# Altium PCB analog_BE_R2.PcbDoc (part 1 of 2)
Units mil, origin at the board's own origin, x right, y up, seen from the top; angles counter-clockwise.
Board outline 3800 x 1200 mil, 2 copper layers (Top Layer, Bottom Layer), stack 62 mil thick; 98 components, 58 nets, 283 pads, 64 vias.
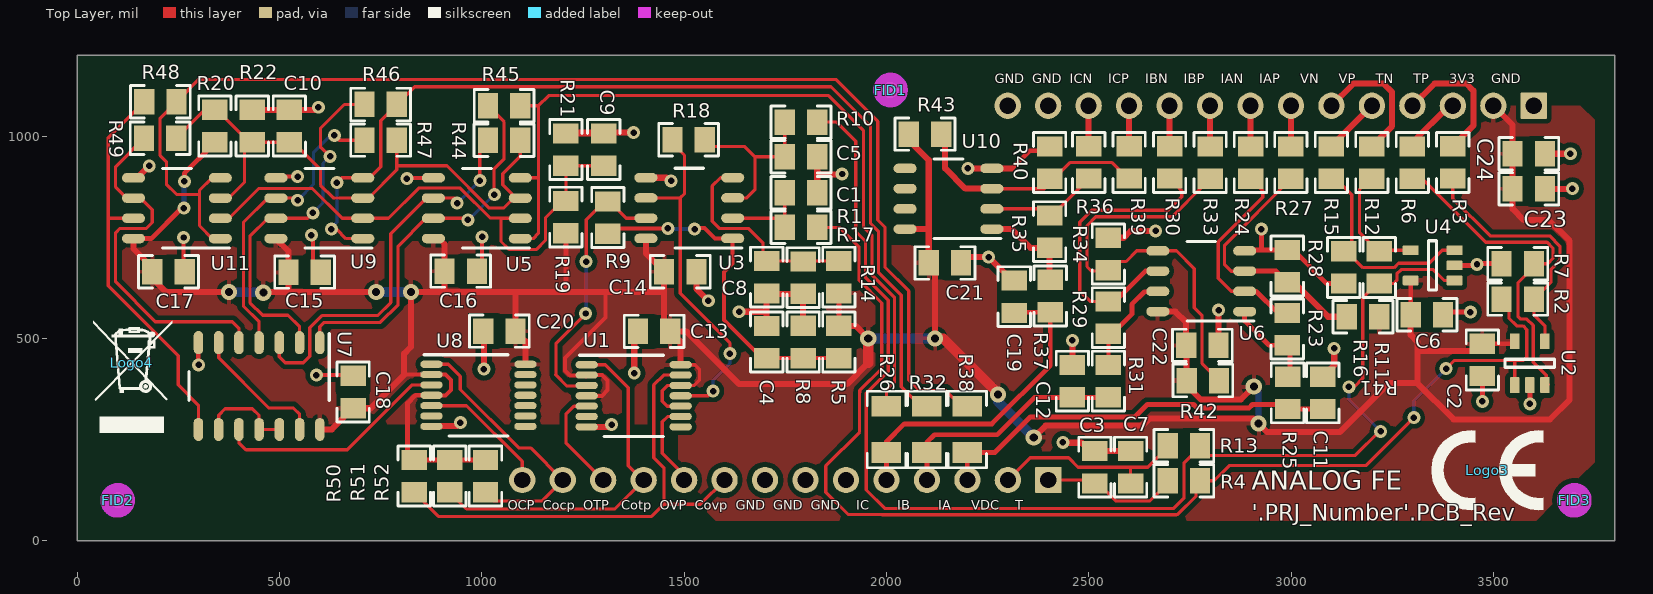
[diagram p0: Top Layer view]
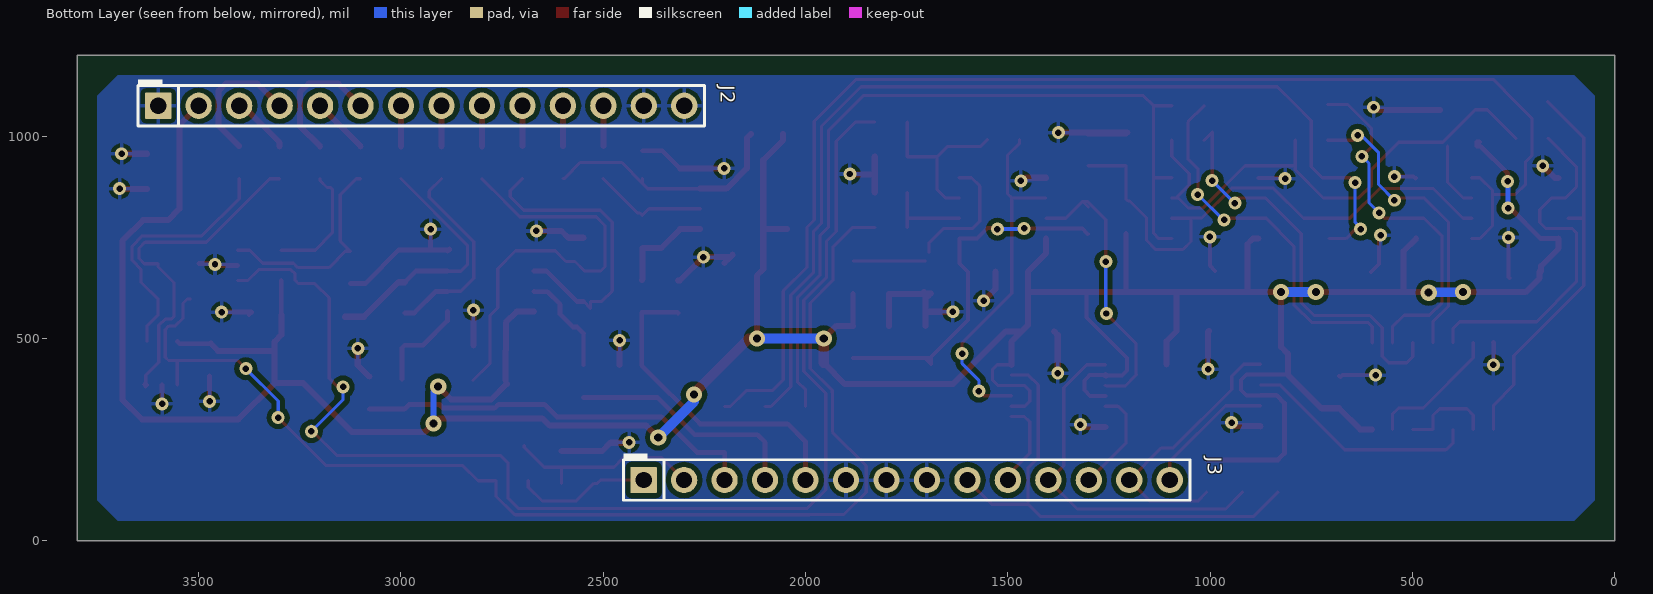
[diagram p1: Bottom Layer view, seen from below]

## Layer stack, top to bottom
Top Solder: solder mask 0.4, Solder Resist, Dk 3.5
Top Layer: signal copper 1.4
Dielectric1: core 59.2, FR-4, Dk 4.8
Bottom Layer: signal copper 1.4
Bottom Solder: solder mask 0.4, Solder Resist, Dk 3.5

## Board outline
0,0 0,1200 3800,1200 3800,0

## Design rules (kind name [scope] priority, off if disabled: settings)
AcuteAngle [All] p1: minimum=4.50000000000000E+0001 checktracksonly=FALSE
AssemblyTestPointUsage [All] p1: valid=2
BoardOutlineClearance BoardOutlineClearance_MountingHoles [OnCopper and InComponentClass('Mounting Holes')] p1: gap=39.37 ignorepadtopadclearanceinfootprint=FALSE
BoardOutlineClearance BoardOutlineClearance_Poly [OnCopper and IsPoly] p2: gap=25 ignorepadtopadclearanceinfootprint=FALSE
BoardOutlineClearance [OnCopper and Not InComponentClass('Logo') and not InComponentClass('FiducialMark') and not InRegion(1000,500,4000,800) and not InPoly] p3: gap=50 ignorepadtopadclearanceinfootprint=FALSE
Clearance Clearance_Keepouts [((IsTrack Or IsArc) And Not InPoly) And IsFree and IsKeepOut vs ((IsTrack Or IsArc) And Not InPoly) And IsFree and IsKeepOut] p1: gap=0 ignorepadtopadclearanceinfootprint=FALSE
Clearance Clearance_Poly [InPolygon] p2: gap=12 ignorepadtopadclearanceinfootprint=TRUE
Clearance Clearance_FiducialMark [IsKeepOut and InComponentClass('FiducialMark') vs IsPad and InComponentClass('FiducialMark')] p3: gap=0 ignorepadtopadclearanceinfootprint=FALSE
Clearance [All] p4: gap=7.87 ignorepadtopadclearanceinfootprint=TRUE
ComponentClearance ComponentClearance_MountingHoles_FiducialMarks [InComponentClass('Mounting Holes') vs InComponentClass('FiducialMark')] p1: gap=50 collisioncheckmode=3 verticalgap=10 showdistances=FALSE
ComponentClearance ComponentClearance_Shunt [InComponentClass('Header') vs InComponentClass('Shunt')] p2: gap=0 collisioncheckmode=3 verticalgap=0 showdistances=FALSE
ComponentClearance ComponentClearance_Logo [InComponentClass('Logo')] p3: gap=50 collisioncheckmode=3 verticalgap=10 showdistances=FALSE
ComponentClearance ComponentClearance_ScrewToNut [(HasFootprint('NY PMS 440 0025 PH')) vs (HasFootprint('Keystone_1902C'))] p4: gap=5 collisioncheckmode=3 verticalgap=10 showdistances=FALSE
ComponentClearance ComponentClearance_MountingHoles [InComponentClass('Mounting Holes')] p5: gap=250 collisioncheckmode=3 verticalgap=100000 showdistances=FALSE
ComponentClearance ComponentClearance_SmallPassives [HasFootprint('0201*') or HasFootprint('0402*') or HasFootprint('0508') or HasFootprint('0603*') or HasFootprint('0612') or HasFootprint('0805*') or HasFootprint('0815*') or HasFootprint('0830*') or HasFootprint('1206*') or HasFootprint('1210*') or HasFootprint('1808*') or HasFootprint('1812*') or HasFootprint('1825*') or HasFootprint('2010*') or HasFootprint('2220*') or HasFootprint('2225*') or HasFootprint('2512*') or HasFootprint('2728*') or HasFootprint('3518*') vs HasFootprint('0201*') or HasFootprint('0402*') or HasFootprint('0508') or HasFootprint('0603*') or HasFootprint('0612') or HasFootprint('0805*') or HasFootprint('0815*') or HasFootprint('0830*') or HasFootprint('1206*') or HasFootprint('1210*') or HasFootprint('1808*') or HasFootprint('1812*') or HasFootprint('1825*') or HasFootprint('2010*') or HasFootprint('2220*') or HasFootprint('2225*') or HasFootprint('2512*') or HasFootprint('2728*') or HasFootprint('3518*')] p6: gap=14.96 collisioncheckmode=3 verticalgap=10 showdistances=FALSE
ComponentClearance ComponentClearance_THtoSMT [IsThruComponent vs IsSMTComponent] p7: gap=40 collisioncheckmode=3 verticalgap=30 showdistances=FALSE
ComponentClearance ComponentClearance_THtoTH [IsThruComponent vs IsThruComponent] p8: gap=30 collisioncheckmode=3 verticalgap=30 showdistances=FALSE
ComponentClearance [All] p9: gap=30 collisioncheckmode=3 verticalgap=10 showdistances=FALSE
DiffPairsRouting [All] p1: maxlimit=100 minlimit=10 mostfreqgap=10 toplayer_minwidth=15 toplayer_maxwidth=15 toplayer_prefwidth=15 bottomlayer_minwidth=15 bottomlayer_maxwidth=15 bottomlayer_prefwidth=15 maxuncoupledlength=1000
FabricationTestPointUsage TestPointUsage [All] p1: valid=2 allowmultiple=FALSE
FabricationTestpoint Testpoint [All] p1: side=3 testpointundercomponent=TRUE minsize=40 maxsize=100 preferedsize=60 minholesize=0 maxholesize=40 preferedholesize=32 testpointgrid=1 allowsidetop=TRUE allowsidebottom=TRUE usegrid=TRUE gridtolerance=0.01
FanoutControl Fanout_LCC [IsLCC] p1: bgadir=Out bgaviamode=Centered fanoutstyle=Auto fanoutdirection=Alternating viagrid=1 // Fanout_LCC (Default Rule)
FanoutControl Fanout_BGA [IsBGA] p2: bgadir=Out bgaviamode=Centered fanoutstyle=Auto fanoutdirection=Alternating viagrid=1 // Fanout_BGA (Default Rule)
FanoutControl Fanout_Default [All] p4: bgadir=Out bgaviamode=Centered fanoutstyle=Auto fanoutdirection=Alternating viagrid=1 // Fanout_Default (Default Rule)
FanoutControl Fanout_Small [(CompPinCount < 5)] p5: bgadir=Out bgaviamode=Centered fanoutstyle=Auto fanoutdirection=OutThenIn viagrid=1 // Fanout_Small (Default Rule)
HoleSize [All] p1: absolutevalues=TRUE maxlimit=251 minlimit=7.87 maxpercent=80.000 minpercent=20.000
MinimumAnnularRing MinimumAnnularRing_ThermalPadVias [IsVia and InAnyComponent] p1: minimumring=5.91
MinimumAnnularRing [All] p2: minimumring=7.87
MinimumSolderMaskSliver MinimumSolderMaskSliver_Logo [InComponentClass('Logo') vs InComponentClass('Logo')] p1: minsoldermaskwidth=0.7
MinimumSolderMaskSliver [All] p2: minsoldermaskwidth=3.94
PlaneClearance [All] p1: clearance=12
PlaneConnect [All] p1: planeconnectstyle=Relief reliefexpansion=10 reliefentries=4 reliefconductorwidth=10 reliefairgap=10
PolygonConnect [All] p1: connectstyle=Relief reliefconductorwidth=10 reliefentries=4 polygonreliefangle="90 Angle" airgapwidth=10
RoutingVias ThermalPadVias [IsVia and InAnyComponent] p1: holewidth=7.87 width=19.68 viastyle="Through Hole" minholewidth=7.87 minwidth=19.68 maxholewidth=12.99 maxwidth=23.62
RoutingVias [All] p2: holewidth=16 width=34 viastyle="Through Hole" minholewidth=7.87 minwidth=26 maxholewidth=40 maxwidth=65
SilkToBoardRegionClearance [Not ((IsComment or IsDesignator) And (Hide <> 'False')) and not InRegion(1000,500,4000,800)] p1:
SilkToSilkClearance SilkToSilkClearance_Pb-FreeLogo [(HasFootprint('Pb-Free_Overlay_Medium') OR HasFootprint('Pb-Free_Overlay_Small')) vs (HasFootprint('Pb-Free_Overlay_Medium') OR HasFootprint('Pb-Free_Overlay_Small'))] p1: silktosilkclearance=0
SilkToSilkClearance [All] p2: silktosilkclearance=3.94
SilkToSolderMaskClearance SilkToComponentPadClearance [(IsPad or IsFill or IsRegion) and InAnycomponent] p1: minsilkscreentomaskgap=5 clearancetoexposedcopper=TRUE
SilkToSolderMaskClearance "Silk to Solder Mask Opening" [All] p2: minsilkscreentomaskgap=3.94 clearancetoexposedcopper=FALSE
SolderMaskExpansion [All] p1: expansion=1.97
UnRoutedNet [All] p1: checkbadconnections=TRUE
Width [All] p1: maxlimit=100 minlimit=6 preferedwidth=10 checkconnectedcopper=TRUE
13 further rules are at their usual default settings.

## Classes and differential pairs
component class Header: J2 J3 p1
component class FiducialMark: FID1 FID2 FID3
component class AssemblyNote: ZZ1 ZZ2 ZZ3 ZZ4
differential pair Vdc: +Vdc_P -Vdc_N
differential pair Temp: +Temp_P -Temp_N
differential pair Ic: +Ic_P -Ic_N
differential pair Ib: +Ib_P -Ib_N
differential pair Ia: +Ia_P -Ia_N

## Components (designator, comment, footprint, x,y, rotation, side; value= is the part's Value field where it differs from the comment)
C1 "08051C103JAT2A" 0805_HV 1788.88,860.33 r0 top value=0.01uF
C2 "GRM219R71C104KA01D" 0805_HV 3472.61,446.92 r270 top value=0.1uF
C3 "08051C103JAT2A" 0805_HV 2515,181.72 r90 top value=0.01uF
C4 "08051A330JAT2A" 0805_HV 1703.92,490.96 r90 top value=33pF
C5 "08051C103JAT2A" 0805_HV 1788.88,949.05 r0 top value=0.01uF
C6 "GRM219R71C104KA01D" 0805_HV 3335.53,558.54 r0 top value=0.1uF
C7 "08051C103JAT2A" 0805_HV 2603.26,181.72 r90 top value=0.01uF
C8 "08051A330JAT2A" 0805_HV 1703.92,651.26 r270 top value=33pF
C9 "08051A330JAT2A" 0805_HV 1301.58,966.62 r90 top value=33pF
C10 "08051A330JAT2A" 0805_HV 524.61,1025 r90 top value=33pF
C11 "08051C103JAT2A" 0805_HV 3077.97,365.45 r90 top value=0.01uF
C12 "08051C103JAT2A" 0805_HV 2459.66,394.41 r90 top value=0.01uF
C13 "GRM219R71C104KA01D" 0805_HV 1425.84,517.29 r0 top value=0.1uF
C14 "GRM219R71C104KA01D" 0805_HV 1490.42,665 r180 top value=0.1uF
C15 "GRM219R71C104KA01D" 0805_HV 562.23,664.06 r180 top value=0.1uF
C16 "GRM219R71C104KA01D" 0805_HV 947.84,666.5 r180 top value=0.1uF
C17 "GRM219R71C104KA01D" 0805_HV 225.81,665 r180 top value=0.1uF
C18 "GRM219R71C104KA01D" 0805_HV 681.74,367.45 r270 top value=0.1uF
C19 "08051C103JAT2A" 0805_HV 2315.58,603.1 r90 top value=0.01uF
C20 "GRM219R71C104KA01D" 0805_HV 1043.31,518.09 r0 top value=0.1uF
C21 "GRM219R71C104KA01D" 0805_HV 2144.42,686.41 r180 top value=0.1uF
C22 "GRM219R71C104KA01D" 0805_HV 2780.65,482.64 r180 top value=0.1uF
C23 "GRM219R71C104KA01D" 0805_HV 3587.32,869.41 r180 top value=0.1uF
C24 "0805YD106MAT2A" 0805_HV 3587.32,956.29 r0 top value=10uF
FID1 "Fiducial" Fiducial10-20 2009.84,1113.85 r0 top
FID2 "Fiducial" Fiducial10-20 100,100 r0 top
FID3 "Fiducial" Fiducial10-20 3700,100 r0 top
J2 "TSW-114-07-G-S" TSW-114-07-G-S 2949.66,1075 r180 bottom
J3 "TSW-114-07-G-S" TSW-114-07-G-S 1750,150 r180 bottom
Logo3 "CE Mark" CE_Mark_5mm 3484.68,174.27 r0 top
Logo4 "WEEE logo" WEEE_Minimum 135,439.71 r0 top
R1 "CRCW0805100RDHEAP" 0805_HV 1788.88,774.42 r180 top value=100
R2 "RT0805BRD0747KL" 0805_HV 3560,597.1 r180 top value=47.0k
R3 "RG2012P-103-B-T5" 0805_HV 3399.66,935 r270 top value=10.0k
R4 "CRCW0805100RDHEAP" 0805_HV 2735,148.21 r180 top value=100
R5 "RR1220P-3321-D-M" 0805_HV 1882.6,491.05 r90 top value=3.32k
R6 "RG2012P-103-B-T5" 0805_HV 3299.66,934.53 r270 top value=10.0k
R7 "RT0805BRD0747KL" 0805_HV 3560,684.76 r0 top value=47.0k
R8 "RG2012P-3322-B-T5" 0805_HV 1794.1,491.05 r270 top value=33.2k
R9 "RR1220P-104-D" 0805_HV 1311.53,798.57 r270 top value=100k
R10 "CRCW0805100RDHEAP" 0805_HV 1788.88,1034.49 r180 top value=100
R11 "RT0805BRD0715KL" 0805_HV 3217.62,675.43 r270 top value=15.0k
R12 "RG2012P-103-B-T5" 0805_HV 3199.66,934.53 r270 top value=10.0k
R13 "CRCW0805100RDHEAP" 0805_HV 2735,235 r180 top value=100
R14 "RR1220P-7871-D-M" 0805_HV 1882.6,651.27 r270 top value=7.87k
R15 "RG2012P-103-B-T5" 0805_HV 3099.66,934.53 r270 top value=10.0k
R16 "RT0805BRD0715KL" 0805_HV 3129.66,675.43 r90 top value=15.0k
R17 "RG2012P-3322-B-T5" 0805_HV 1794.1,650.11 r90 top value=33.2k
R18 "RR1220P-104-D" 0805_HV 1511.15,990.85 r0 top value=100k
R19 "RR1220P-3321-D-M" 0805_HV 1207.81,799.63 r270 top value=3.32k
R20 "RG2012P-3322-B-T5" 0805_HV 340.37,1025 r270 top value=33.2k
R21 "RG2012P-3322-B-T5" 0805_HV 1207.81,966.62 r270 top value=33.2k
R22 "RR1220P-3321-D-M" 0805_HV 432.65,1025 r90 top value=3.32k
R23 "RT0805BRD077K5L" 0805_HV 2990.51,523.1 r270 top value=7.50k
R24 "MCU0805MD1002BP100" 0805_HV 2899.66,934.53 r270 top value=10.0k
R25 "CRCW0805100RDHEAP" 0805_HV 2991.08,365.45 r270 top value=100
R26 "CRCW12061K00FKEA" 1206 2000,275 r90 top value=1.00k
R27 "MCU0805MD1002BP100" 0805_HV 2999.66,934.53 r270 top value=10.0k
R28 "RT0805BRD0715KL" 0805_HV 2990.51,678.81 r270 top value=15.0k
R29 "RT0805BRD077K5L" 0805_HV 2548.35,551.37 r270 top value=7.50k
R30 "MCU0805MD1002BP100" 0805_HV 2699.66,935 r270 top value=10.0k
R31 "CRCW0805100RDHEAP" 0805_HV 2548.35,394.41 r270 top value=100
R32 "CRCW12061K00FKEA" 1206 2100,275 r90 top value=1.00k
R33 "MCU0805MD1002BP100" 0805_HV 2799.76,934.53 r270 top value=10.0k
R34 "RT0805BRD0715KL" 0805_HV 2548.35,708.7 r270 top value=15.0k
R35 "RT0805BRD077K5L" 0805_HV 2403.18,763.89 r270 top value=7.50k
R36 "MCU0805MD1002BP100" 0805_HV 2499.66,935 r270 top value=10.0k
R37 "CRCW0805100RDHEAP" 0805_HV 2404.66,604.81 r270 top value=100
R38 "CRCW12061K00FKEA" 1206 2199.66,275 r90 top value=1.00k
R39 "MCU0805MD1002BP100" 0805_HV 2599.66,935 r270 top value=10.0k
R40 "RT0805BRD0715KL" 0805_HV 2403.18,934.53 r270 top value=15.0k
R41 "RT0805BRD0715KL" 0805_HV 3177.62,553.6 r180 top value=15.0k
R42 "RT0805BRD0715KL" 0805_HV 2781.94,395.95 r0 top value=15.0k
R43 "RT0805BRD0715KL" 0805_HV 2095.22,1005 r0 top value=15.0k
R44 "RR1220P-104-D" 0805_HV 1055.03,989.91 r0 top value=100k
R45 "RR1220P-104-D" 0805_HV 1055.14,1075 r180 top value=100k
R46 "RR1220P-104-D" 0805_HV 750,1078.07 r180 top value=100k
R47 "RR1220P-104-D" 0805_HV 750,990 r0 top value=100k
R48 "RR1220P-104-D" 0805_HV 205.63,1085 r180 top value=100k
R49 "RR1220P-104-D" 0805_HV 205,994.43 r180 top value=100k
R50 "RT0805BRD0715KL" 0805_HV 832.83,159.81 r90 top value=15.0k
R51 "RT0805BRD0715KL" 0805_HV 920.58,159.81 r90 top value=15.0k
R52 "RT0805BRD0715KL" 0805_HV 1009.12,159.81 r90 top value=15.0k
U1 "SN74LVC74AQPWRQ1" PW0014A_N 1375.34,358.23 r0 top
U2 "TLV6001IDBVR" DBV0005A_N 3589.92,438.81 r90 top
U3 "TLV3502AID" D0008A_N 1512.77,822.11 r180 top
U4 "TLV6001IDBVR" DBV0005A_N 3349.66,680.49 r180 top
U5 "TLV3502AID" D0008A_N 987.74,821.8 r180 top
U6 "OPA2350UA/2K5" D0008A_N 2777.88,641.37 r180 top
U7 "CD74HC4075MT" D0014A_N 449.66,382.28 r270 top
U8 "SN74LVC74AQPWRQ1" PW0014A_N 991.67,359.41 r0 top
U9 "TLV3502AID" D0008A_N 598.5,821.8 r180 top
U10 "OPA2350UA/2K5" D0008A_N 2153.18,845.15 r180 top
U11 "TLV3502AID" D0008A_N 246.54,821.8 r180 top
ZZ1 "This Assembly Note is for PCB labels only" AssemblyNoteLabel 185,3938 r0 top
ZZ2 "These assemblies are ESD sensitive, ESD precautions shall be observed." AssemblyNote 185,3829.11 r0 top
ZZ3 "These assemblies must be clean and free from flux and all contaminants. Use of no clean flux is not acceptable." AssemblyNote 185,3740.56 r0 top
ZZ4 "These assemblies must comply with workmanship standards IPC-A-610 Class 2, unless otherwise specified." AssemblyNote 185,3652 r0 top

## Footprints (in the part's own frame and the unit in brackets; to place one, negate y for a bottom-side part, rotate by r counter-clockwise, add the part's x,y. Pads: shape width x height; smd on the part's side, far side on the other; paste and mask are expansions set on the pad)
0805_HV [mil] "0805 with 30mil clearance between pads"
  rect 50x63 smd: 1(-40,0) 2(40,0)
  silkscreen extent -74,-40 74,40, body extent -43,-29 43,29, height 57
1206 [mm] "1206 from SM-752 data"
  rect 1.3x1.85 smd: 1(-1.45,0) 2(1.45,0)
  silkscreen extent -2.4,-1.21 2.4,1.21, body extent -1.7,-0.9 1.7,0.9, height 1.35
AssemblyNote [mil] "Assembly Note"
AssemblyNoteLabel [mil] "Assembly Note for PCB Labels"
CE_Mark_5mm [mil] "Minimum text height for CE Mark"
  silkscreen extent -138,-98 138,98
D0008A_N [mm] "SOIC, 8-Leads, Body 4.9x3.9mm, Pitch 1.27mm, IPC Medium Density"
  oval 1.45x0.6 smd: 1(-2.725,1.905) 2(-2.725,0.635) 3(-2.725,-0.635) 4(-2.725,-1.905) 5(2.725,-1.905) 6(2.725,-0.635) 7(2.725,0.635) 8(2.725,1.905)
  silkscreen extent -3.3,-2.5 0.9,2.5, body extent -3,-2.45 3,2.45, height 1.63
D0014A_N [mm] "SOIC, 14-Leads, Body 8.7x3.9mm, Pitch 1.27mm, IPC Medium Density"
  oval 1.45x0.6 smd: 1(-2.725,3.81) 2(-2.725,2.54) 3(-2.725,1.27) 4(-2.725,0) 5(-2.725,-1.27) 6(-2.725,-2.54) 7(-2.725,-3.81) 8(2.725,-3.81) 9(2.725,-2.54) 10(2.725,-1.27) 11(2.725,0) 12(2.725,1.27) 13(2.725,2.54) 14(2.725,3.81)
  silkscreen extent -3.3,-4.4 0.9,4.4, body extent -3.02,-4.32 3.02,4.32, height 1.6
DBV0005A_N [mm] "SOT23, 5-Leads, Body 2.9x1.6mm, Pitch 0.95mm, Lead Span 2.8mm, IPC Medium Density"
  rrect17% 1x0.6 smd: 1(-1.375,0.95) 2(-1.375,0) 3(-1.375,-0.95) 4(1.375,-0.95) 5(1.375,0.95)
  silkscreen extent -0.25,-1.55 0.25,1.55, body extent -1.42,-1.46 1.42,1.46, height 1.09
Fiducial10-20 [mm]
  round 1 smd mask+0.5: 1(0,0)
  Top Layer keep-out circle w1.178: c0,0 r0.5
PW0014A_N [mm] "TSOP, 14-Leads, Body 5x4.4mm, Pitch 0.65mm, IPC Medium Density"
  oval 1.4x0.45 smd: 1(-2.95,1.95) 2(-2.95,1.3) 3(-2.95,0.65) 4(-2.95,0) 5(-2.95,-0.65) 6(-2.95,-1.3) 7(-2.95,-1.95) 8(2.95,-1.95) 9(2.95,-1.3) 10(2.95,-0.65) 11(2.95,0) 12(2.95,0.65) 13(2.95,1.3) 14(2.95,1.95)
  silkscreen extent -3.4,-2.55 1.85,2.55, body extent -3.21,-2.5 3.21,2.5, height 1
TSW-114-07-G-S [mm] "Samtec 100mil, 1x14, 230 mil above insulator"
  rrect6% 1.65x1.65 hole 1.016: 1(-16.51,0)
  round 1.65 hole 1.016: 2(-13.97,0) 3(-11.43,0) 4(-8.89,0) 5(-6.35,0) 6(-3.81,0) 7(-1.27,0) 8(1.27,0) 9(3.81,0) 10(6.35,0) 11(8.89,0) 12(11.43,0) 13(13.97,0) 14(16.51,0)
  silkscreen extent -17.78,-1.27 17.78,1.65, body extent -17.78,-1.27 17.78,1.27, height 8.38
WEEE_Minimum [mil] "WEEElie bin"
  silkscreen extent -95,-172 99,104

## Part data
C1 C3 C5 C7 C11 C12 C19: library part CMP-0007542-1, "CAP, CERM, 0.01 uF, 100 V, +/- 5%, X7R, 0805", Cap_Case=0805, Manufacturer=AVX, Supplier Part Number 1=478-3745-1-ND, TempCo=X7R, Tolerance_%=5%, Value1="0.078 ohm", Value2=100V, ValueDisplayed=0.01uF
C2 C6 C13 C14 C15 C16 C17 C18 C20 C21 C22 C23: library part CMP-0008209-1, "CAP, CERM, 0.1 uF, 16 V, +/- 10%, X7R, 0805", Cap_Case=0805, Manufacturer=MuRata, Supplier Part Number 1=490-1683-1-ND, TempCo=X7R, Tolerance_%=10%, Value1=Unknown, Value2=16V, ValueDisplayed=0.1uF
C4 C8 C9 C10: library part CMP-0007529-1, "CAP, CERM, 33 pF, 100 V, +/- 5%, C0G/NP0, 0805", Cap_Case=0805, Manufacturer=AVX, Supplier Part Number 1=478-1281-1-ND, TempCo=C0G/NP0, Tolerance_%=5%, Value1="0.708 ohm", Value2=100V, ValueDisplayed=33pF
C24: library part CMP-0007678-2, "CAP, CERM, 10 uF, 16 V, +/- 20%, X5R, 0805", Cap_Case=0805, Manufacturer=AVX, Supplier Part Number 1=1582704, TempCo=X5R, Tolerance_%=20%, Value1=Unknown, Value2=16V, ValueDisplayed=10uF
FID1 FID2 FID3: library part CMP-0077181-1, "Fiducial mark.  There is nothing to buy or mount.", Manufacturer=N/A
J2 J3: library part CMP-0075428-1, "Header, 100mil, 14x1, Gold, TH", Color=Black, Current_A=6.3A, Manufacturer=Samtec, Supplier Part Number 1=SAM1029-14-ND, Voltage_V=550V
Logo3: library part CMP-0074844-1
Logo4: library part CMP-0074769-1
R1 R4 R10 R13 R25 R31 R37: library part CMP-0065350-1, "RES, 100, .5%, .125 W, AEC-Q200 Grade 0, 0805", Manufacturer=Vishay-Dale, Power_W=125mW, Supplier Part Number 1=541-100AZCT-ND, TempCo="50 ppm/C", Tolerance_%=0.5%, Value1=.5%, Value2=.125W, Value_Code=100R, ValueDisplayed=100
R2 R7: library part CMP-0020108-1, "RES, 47.0 k, 0.1%, 0.125 W, 0805", Manufacturer="Yageo America", Power_W=125mW, Supplier Part Number 1=9983074, TempCo="25 ppm/C", Tolerance_%=0.1%, Value2=0.125W, Value_Code=47k0, ValueDisplayed=47.0k
R3 R6 R12 R15: library part CMP-0018856-1, "RES, 10.0 k, 0.1%, 0.125 W, 0805", Manufacturer="Susumu Co Ltd", Power_W=125mW, Supplier Part Number 1=RG20P10.0KBCT-ND, TempCo="25 ppm/C", Tolerance_%=0.1%, Value2=0.125W, Value_Code=10k0, ValueDisplayed=10.0k
R5 R19 R22: library part CMP-0019250-1, "RES, 3.32 k, 0.5%, 0.1 W, 0805", Manufacturer="Susumu Co Ltd", Power_W=100mW, Supplier Part Number 1=RR12P3.32KDCT-ND, TempCo="25 ppm/C", Tolerance_%=0.5%, Value2=0.1W, Value_Code=3k32, ValueDisplayed=3.32k
R8 R17 R20 R21: library part CMP-0018959-1, "RES, 33.2 k, 0.1%, 0.125 W, 0805", Manufacturer="Susumu Co Ltd", Power_W=125mW, Supplier Part Number 1=RG20P33.2KBCT-ND, TempCo="25 ppm/C", Tolerance_%=0.1%, Value2=0.125W, Value_Code=33k2, ValueDisplayed=33.2k
R9 R18 R44 R45 R46 R47 R48 R49: library part CMP-0019096-1, "RES, 100 k, 0.5%, 0.1 W, 0805", Manufacturer="Susumu Co Ltd", Power_W=100mW, Supplier Part Number 1=RR12P100KDCT-ND, TempCo="25 ppm/C", Tolerance_%=0.5%, Value2=0.1W, Value_Code=100k
R11 R16 R28 R34 R40 R41 R42 R43 R50 R51 R52: library part CMP-0019589-2, "RES, 15.0 k, 0.1%, 0.125 W, 0805", Manufacturer="Yageo America", Power_W=125mW, Supplier Part Number 1=9982876, TempCo="25 ppm/C", Tolerance_%=0.1%, Value2=0.125W, Value_Code=15k0, ValueDisplayed=15.0k
R14: library part CMP-0019362-2, "RES, 7.87 k, 0.5%, 0.1 W, 0805", Manufacturer="Susumu Co Ltd", Power_W=100mW, Supplier Part Number 1=RR12P7.87KDCT-ND, TempCo="25 ppm/C", Tolerance_%=0.5%, Value2=0.1W, Value_Code=7k87, ValueDisplayed=7.87k
R23 R29 R35: library part CMP-0020336-2, "RES, 7.50 k, 0.1%, 0.125 W, 0805", Manufacturer="Yageo America", Power_W=125mW, TempCo="25 ppm/C", Tolerance_%=0.1%, Value2=0.125W, Value_Code=7k50, ValueDisplayed=7.50k
R24 R27 R30 R33 R36 R39: library part CMP-0018838-2, "RES, 10.0 k, 0.1%, 0.2 W, AEC-Q200 Grade 0, 0805", Manufacturer=Vishay/Beyschlag, Power_W=200mW, Supplier Part Number 1=MCU0805-10.0K-MBCT-ND, TempCo="25 ppm/C", Tolerance_%=0.1%, Value2=0.2W, Value_Code=10k0, ValueDisplayed=10.0k
R26 R32 R38: library part CMP-0016687-3, "RES, 1.00 k, 1%, 0.25 W, AEC-Q200 Grade 0, 1206", Manufacturer=Vishay-Dale, Power_W=250mW, Supplier Part Number 1=541-1.00KFCT-ND, TempCo="100 ppm/C", Tolerance_%=1%, Value2=0.25W, Value_Code=1k00, ValueDisplayed=1.00k
U1 U8: library part CMP-0048843-1, "Automotive Catalog Dual Positive-Edge-Triggered D-Type Flip-Flops With Clear And Preset, PW0014A, LARGE T&R", F @ Nom Voltage(Max)(Mhz)=100, Generic Part Number=SN74LVC74A-Q1, ICC @ Nom Voltage(Max)(mA)=0.01, Manufacturer="Texas Instruments", Operating Temperature Range(C)="-40 to 125", PartNumber=SN74LVC74AQDRG4Q1, Rating=Automotive, tpd @ Nom Voltage(Max)(ns)=6,5.2, Voltage(Nom)(V)=2.7,3.3
U2 U4: library part CMP-0073547-1, "1-MHz, Low-Power Operational Amplifier for Cost-Sensitive Systems, DBV0005A (SOT-23-5)", Alternate Manufacturer="Texas Instruments", Alternate PartNumber=TLV6001IDBVT
U3 U5 U9 U11: library part CMP-0065423-1, "4.5ns Rail-to-Rail Comparator, D0008A (SOIC-8)", Alternate Manufacturer="Texas Instruments"
U6 U10: library part CMP-0040782-1, "High-Speed, Single-Supply, Rail-to-Rail Operational Amplifier MicroAmplifier(TM) Series, 2.7 to 5.5 V, -40 to 85 degC, 8-pin SOIC (D8), Green (RoHS & no Sb/Br)", Manufacturer="Texas Instruments", Total Supply Voltage(Max)(+5V is 5, +/-5V is 10)=5.5, Total Supply Voltage(Min)(+5V is 5, +/-5V is 10)=2.7
U7: library part CMP-0050748-1, "High Speed CMOS Logic Triple 3-Input OR Gates, D0014A, SMALL T&R", F @ Nom Voltage(Max)(Mhz)=70, Generic Part Number=CD74HC4075, ICC @ Nom Voltage(Max)(mA)=0.02, Manufacturer="Texas Instruments", Operating Temperature Range(C)="-55 to 125", Rating=Catalog, tpd @ Nom Voltage(Max)(ns)=25, Voltage(Nom)(V)=5
ZZ1: library part CMP-0003616-3
ZZ2: library part CMP-0077236-1
ZZ3: library part CMP-0077237-1
ZZ4: library part CMP-0077238-1

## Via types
v1: diameter 32, hole 16, Top Layer to Bottom Layer, 54 vias
v2: diameter 40, hole 20, Top Layer to Bottom Layer, 10 vias

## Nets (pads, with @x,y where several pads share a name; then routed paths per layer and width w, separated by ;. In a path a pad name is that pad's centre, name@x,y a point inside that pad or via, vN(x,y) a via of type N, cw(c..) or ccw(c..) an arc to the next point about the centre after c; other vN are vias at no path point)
3.3V: C2.1 C6.1 C13.2 C14.2 C15.2 C16.2 C17.2 C18.2 C20.2 C21.2 C22.2 C23.2 C24.1 J2.2 R5.2 R14.2 R19.2 R20.2 R41.1 R42.1 R43.1 R50.2 R51.2 R52.2 U1.2 U1.4 U1.10 U1.12 U1.14 U2.5 U3.8 U4.5 U5.8 U6.8 U7.14 U8.2 U8.4 U8.14 U9.8 U10.8 U11.8 | length 9710
  Top Layer w8: U1.10@1491.48,332.64 1457.78,332.64 1446.11,344.31 1446.11,370.5 1459.42,383.82 U1.12@1491.48,383.82 1525.42,383.82 1537.76,396.16 1537.76,423.95 1526.7,435 U1.14@1491.48,435
  Top Layer w10: 807.84,410 808.43,410.59 U8.2@875.53,410.59 910.76,410.59 924,397.35 924,372.65 910.76,359.41 U8.4@875.53,359.41 ; U1.2@1257.84,408.05 1217.95,408.05 1205.14,420.86 1205.14,451.81 1305.14,551.81 1305.14,614.36 1305,614.5 ; U1.4@1259.2,358.23 1297.23,358.23 1311.15,372.15 1311.15,395.85 1297.59,409.41 U1.2@1259.2,409.41
  Top Layer w12: U11.8@139.25,746.8 182.62,746.8 257.93,822.11 v1(263.96,822.11) ; v1(265,888.06) 265,908.03 331.97,975 340.37,975 R20.2@340.37,985 R20.2@334.37,985 ; U8.4@875.53,359.41 835.84,359.41 816.65,340.22 816.65,216 R50.2@832.83,199.81 R51.2@920.58,199.81 R52.2@1009.12,199.81 ; 1207.81,614.5 R19.2@1207.81,759.63 ; R5.2@1882.6,531.05 R14.2@1882.6,611.27 ; C6.1@3295.53,558.54 U4.5@3295.53,642.87 ; C2.1@3469.31,486.92 C2.1@3472.61,486.92 3546.49,486.92 U2.5@3552.52,492.94
  Top Layer w15: U11.8@139.25,746.8 139.25,721.8 182.52,678.54 C17.2@182.52,665 ; C17.2@185.81,665 185.81,649.19 220.58,614.42 v2(375,614.42) ; v2@469.44,614.42 524.66,614.42 ; U9.8@491.21,746.8 522.23,715.79 C15.2@522.23,664.06 522.23,616.85 524.66,614.42 ; U7.14@599.66,275 629.28,275 C18.2@681.74,327.45 725.29,327.45 807.84,410 807.84,462.27 825,479.43 v2(825,614.5) ; v2@744,614.42 v2(739,614.42) 524.66,614.42 ; v2@839.26,614.42 907.84,614.42 ; U5.8@880.46,746.8 894.39,746.8 907.84,733.35 C16.2@907.84,666.5 907.84,614.42 ; 1083.31,613.8 C20.2@1083.31,518.09 1107.81,493.59 U8.14@1107.81,436.18 ; U1.2@1257.84,408.05 U1.2@1259.2,409.41 ; U3.8@1405.49,747.11 1405.49,709.93 C14.2@1450.42,665 1450.42,532.71 C13.2@1465.84,517.29 ; 1449.66,614.5 1305,614.5 1207.81,614.5 1083.31,614.5 1083.23,614.42 907.84,614.42 ; U1.14@1491.48,435 1491.48,491.64 C13.2@1465.84,517.29 ; R5.2@1882.6,531.05 1923.71,531.05 v2(1955,499.77) ; 1955,439.4 1902.6,387 1635.76,387 1505.47,517.29 C13.2@1465.84,517.29 ; U10.8@2045.9,770.15 2104.27,770.15 2104.42,770 ; R43.1@2055.22,1005 2055.22,989.78 2104.42,940.58 2104.42,770 ; v2(2120,500) 2120,655.7 2104.42,671.28 2105,671.85 2104.42,672.43 C21.2@2104.42,686.41 2104.42,770 ; v2(2364.03,255.36) 2364.43,255.36 2393.51,284.45 2632.64,284.45 2650.39,302.19 2907.18,302.19 v2(2919.6,289.77) 2940.98,268.38 3120.4,268.38 3241.48,389.46 3312.21,389.46 ; U6.8@2670.59,566.37 2714.12,566.37 2740.65,539.84 C22.2@2740.65,482.64 2740.65,471.72 2741.94,470.43 R42.1@2741.94,395.95 ; R42.1@2738.45,387.5 2776.87,349.08 2875.98,349.08 v2(2907.84,380.94) ; C6.1@3295.53,558.54 3295.53,508.95 3312.21,492.28 3312.21,470 ; C2.1@3469.31,486.92 3451.37,468.98 3313.23,468.98 3312.21,470 ; J2.2@3499.66,1075 3547.32,1027.34 C24.1@3547.32,956.29 C23.2@3547.32,869.41 3547.32,820.11 3575.19,792.24 3636.87,792.24 3688.05,741.06 3688.05,348.35 3639.7,300 3401.67,300 3312.21,389.46 ; 3312.21,389.46 3312.21,470
  Top Layer w25: 1955,439.4 v2(1955,499.77) ; v2(2120,500) 2140.22,500 2275.58,364.63 v2(2275.58,361.18)
  Bottom Layer w12: v1(263.96,822.11) 263.96,885.4 265.81,887.25 v1(265,888.06)
  Bottom Layer w15: v2@824.92,614.42 v2(825,614.5) ; v2(2907.84,380.94) 2919.6,369.17 v2(2919.6,289.77)
  Bottom Layer w25: v2(375,614.42) v2(460,613) ; v2@744,614.42 v2@824.92,614.42 ; v2(1955,499.77) 2120,499.77 2120.23,499.77 v2(2120,500) ; v2(2275.58,361.18) 2275.58,343.81 v2(2364.03,255.36)
Clr_OCP_Latch: J3.13 R52.1 U8.1 | length 683.3
  Top Layer w8: U8.1@875.53,436.18 916.82,436.18 947,406 947,373.77 1091.27,229.5 1120.5,229.5 J3.13@1200,150 1148,98 1030.93,98 R52.1@1009.12,119.81
Clr_OTP_Latch: J3.11 R51.1 U1.1 | length 897.1
  Top Layer w8: R51.1@920.58,119.81 962.02,78.38 1328.38,78.38 J3.11@1398.59,148.59 ; U1.1@1259.2,435 1304.75,435 1361.84,377.92 1361.84,185.34 J3.11@1398.59,148.59 ; J3.11@1400,150 J3.11@1398.59,148.59
Clr_OVP_Latch: J3.9 R50.1 U1.13 | length 1210.8
  Top Layer w8: R50.1@832.83,119.81 892.65,60 1419.66,60 1450,90.34 ; U1.13@1491.48,409.41 1449.41,409.41 1425,385 1425,205.15 1450,180.15 1450,90.34 ; J3.9@1600,150 1540.34,90.34 1450,90.34
GND: C1.2 C2.2 C3.2 C4.2 C5.2 C6.2 C7.2 C8.2 C9.2 C10.2 C11.2 C12.2 C13.1 C14.1 C15.1 C16.1 C17.1 C18.1 C19.2 C20.1 C21.1 C22.1 C23.1 C24.2 J2.1 J2.13 J2.14 J3.6 J3.7 J3.8 R7.1 R8.1 R16.1 R17.1 R21.1 R22.2 R28.1 R34.1 R40.1 U1.7 U2.2 U3.5 U4.2 U5.5 U6.4 U7.7 U8.7 U9.5 U10.4 U11.5 | length 3747.4
  Top Layer w10: C17.1@260.26,649.72 262.86,652.32 v1(262.86,749.4) ; U9.5@491.21,896.8 492.54,895.47 497.07,900 v1(545,900) ; v1(578.85,755.26) 578.85,751.15 582.7,747.3 582.7,683.59 C15.1@602.23,664.06 ; v1(591.43,409.12) 673.4,409.12 678.4,404.12 C18.1@681.74,407.45 ; v1(815,895) 816.8,896.8 U5.5@880.46,896.8 ; C16.1@987.84,666.5 1000.95,679.61 v1(1000.95,751.15) v1@991.55,751.15
  Top Layer w12: U7.7@299.66,489.57 299.42,489.33 299.42,427.2 300,427.78 v1(300,434.41) ; 2310.46,920.15 2353.91,963.6 R40.1@2403.18,963.6 ; U6.4@2879.82,718.81 U6.4@2882.72,718.81 ; U6.4@2879.81,721.72 U6.4@2882.72,718.81 ; U6.4@2885.16,716.37 U6.4@2882.72,718.81 ; v1(2926.38,770) 2926.38,718.81 ; R16.1@3124.66,635.43 3088.41,635.43 3005.03,718.81 R28.1@2990.51,718.81 2926.38,718.81 ; C6.2@3375.53,558.54 3369.07,565 v1(3442.99,565) ; U4.2@3403.8,680.49 3404.29,680 3456.52,680 v1(3459.35,682.83) 3461.28,684.76 R7.1@3499.66,684.76 ; v1(3472.61,344.48) C2.2@3472.61,406.92 ; v1(3589.92,338.35) U2.2@3589.92,384.67 ; U6.4@2882.72,718.81 2926.38,718.81
  Top Layer w15: U11.5@139.25,896.8 148.3,896.8 v1(178.12,926.62) ; R22.2@432.65,1065 C10.2@524.61,1065 589.75,1065 v1(596.04,1071.29) ; U8.7@875.53,282.64 876.89,284 939,284 v1(947,292) ; C20.1@1003.31,518.09 1005,516.4 v1(1005,424) ; R21.1@1204.57,1008.53 v1(1375,1008.53) ; R21.1@1207.81,1006.62 C9.2@1301.58,1006.62 ; U1.7@1259.2,281.46 1315.46,281.46 v1(1321,287) ; v1(1376.71,414.23) 1376.71,508.16 C13.1@1385.84,517.29 ; U3.5@1405.49,897.11 1455.98,897.11 1463.56,889.53 v1(1467.84,889.53) ; C14.1@1530.42,665 1530.42,622.38 v1(1559.7,593.1) ; v1(1635.77,565.95) 1703.92,565.95 ; C4.2@1703.92,530.96 1703.92,565.95 ; C8.2@1707.66,615 C8.2@1703.92,611.26 ; R8.1@1794.1,531.05 R17.1@1794.1,610.11 1705.07,610.11 C8.2@1703.92,611.26 ; C1.2@1828.88,860.33 1828.88,904.69 ; C5.2@1828.88,949.05 1828.88,904.69 ; v1(1890.25,906.29) 1888.64,904.69 1828.88,904.69 ; C21.1@2180,706.83 C21.1@2185.81,701.02 ; C21.1@2200.46,686.37 C21.1@2185.81,701.02 ; v1(2201.26,920.15) U10.4@2260.46,920.15 2310.46,920.15 ; C19.2@2315.58,643.1 2310.42,643.1 v1(2252.5,701.02) C21.1@2185.81,701.02 ; v1(2435.97,243.11) 2436.91,242.17 2482.17,242.17 2502.62,221.72 C3.2@2515,221.72 C7.2@2603.26,221.72 ; v1(2459.52,495) 2459.66,494.87 C12.2@2459.66,434.41 ; R34.1@2548.35,748.7 2586.23,748.7 2603.02,765.49 v1(2665,765.49) ; C22.1@2820.65,482.64 v1(2820.65,570.01) ; C11.2@3077.97,405.45 3106.52,433.99 v1(3106.52,475.18) ; C23.1@3627.32,869.41 v1@3685.31,869.41 ; C24.2@3627.32,956.29 v1(3690.31,956.29) ; 1703.92,565.95 C8.2@1703.92,611.26 ; C8.2@1703.92,611.26 1697.07,604.42 1690.23,611.26 C8.2@1703.92,611.26
  other v1: 3695,870
Ia_N: J2.8 R24.1 | length 100.5
  Top Layer w15: R24.1@2899.66,974.53 J2.8@2899.66,1075
Ia_P: J2.7 R27.1 | length 100.5
  Top Layer w15: R27.1@2999.66,974.53 J2.7@2999.66,1075
Ib_N: J2.10 R30.1 | length 100
  Top Layer w15: R30.1@2699.66,975 J2.10@2699.66,1075
Ib_P: J2.9 R33.1 | length 100.5
  Top Layer w15: J2.9@2799.66,1075 2799.66,974.64 R33.1@2799.76,974.53
Ic_N: J2.12 R36.1 | length 100
  Top Layer w15: R36.1@2499.66,975 J2.12@2499.66,1075
Ic_P: J2.11 R39.1 | length 100
  Top Layer w15: R39.1@2599.66,975 J2.11@2599.66,1075
Ifb_A: C11.1 J3.3 R25.2 R38.1 | length 1007.8
  Top Layer w12: J3.3@2200,150 2199.66,150.34 2199.66,218.11 2268.11,218.11 2355.82,305.82 2614.03,305.82 2644.94,336.72 2759,336.72 2768.02,327.7 2895.61,327.7 2904.63,336.72 2979.81,336.72 R25.2@2991.08,325.45 C11.1@3077.97,325.45
Ifb_B: C12.1 J3.4 R31.2 R32.1 | length 587.6
  Top Layer w12: J3.4@2100,150 2100,218.11 2100,243.11 2118.66,261.77 2273.59,261.77 2366.22,354.41 C12.1@2459.66,354.41 R31.2@2548.35,354.41
Ifb_C: C19.1 J3.5 R26.1 R37.2 | length 799.2
  Top Layer w12: J3.5@2000,150 2000,218.11 2000,245 2043.86,288.86 2260.63,288.86 2404.66,432.89 R37.2@2404.66,564.81 2317.29,564.81 C19.1@2315.58,563.1
MtrTmpFbk: C3.1 J3.1 R4.2 | length 336.3
  Top Layer w8: J3.1@2400,150 2506.72,150 C3.1@2515,141.72 2523.01,141.72 2566.3,98.43 2651.22,98.43 2684.96,132.18 R4.2@2684.96,148.21
NetC1_1: C1.1 R1.2 U3.2 | length 215.5
  Top Layer w8: U3.2@1620.06,797.11 R1.2@1747.1,797.11 ; 1747.1,822.11 1748.88,820.33 ; R1.2@1748.88,774.42 1748.88,820.33 ; C1.1@1748.88,860.33 1748.88,820.33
